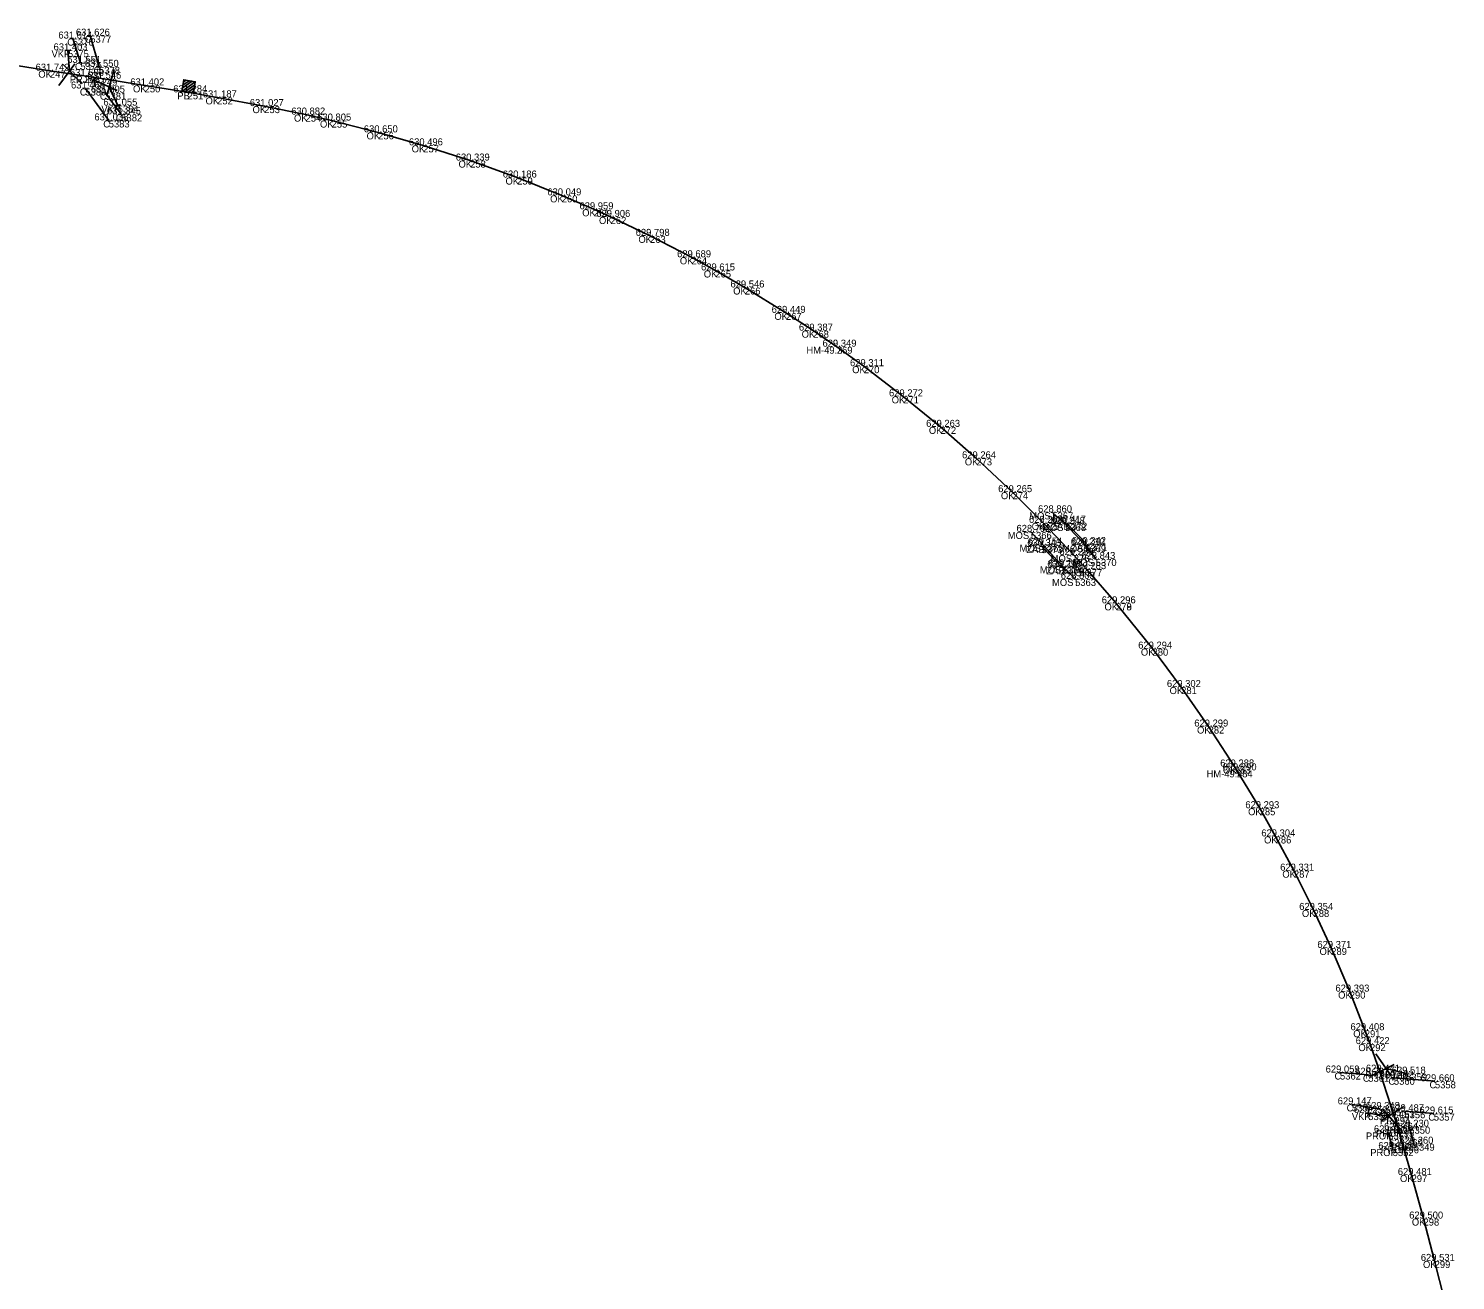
# Model space of a CAD drawing. Extents: x -631472 to -620808, y -1122356 to -1115125.
# Drawn here: x -629803.1 to -629559.3, y -1115505.1 to -1115291.1 of the extents above; entities that cross this region are included whole.
import ezdxf

# ---------------------------------------------------------------- set-up
doc = ezdxf.new("R2010")
doc.units = 0
for name, color, linetype in [('Vrstva 1', 7, 'Continuous'), ('Vrstva 17', 7, 'Continuous'), ('Vrstva 18', 7, 'Continuous'), ('Vrstva 3', 7, 'Continuous'), ('Vrstva 4', 7, 'Continuous'), ('Vrstva 51', 7, 'Continuous'), ('Vrstva 60', 7, 'Continuous'), ('Vrstva 61', 7, 'Continuous'), ('Vrstva 62', 7, 'Continuous')]:
    doc.layers.add(name, color=color, linetype=linetype)

msp = doc.modelspace()

# ---------------------------------------------------------------- linework, layer by layer
at = {"layer": 'Vrstva 1'}
msp.add_lwpolyline([(-629807.63, -1115297.05), (-629799.41, -1115298.32), (-629793.54, -1115299.22), (-629790.58, -1115299.68), (-629783.23, -1115300.83), (-629775.89, -1115302.01), (-629770.85, -1115302.88), (-629762.81, -1115304.37), (-629755.74, -1115305.82), (-629751.29, -1115306.84), (-629743.34, -1115308.86), (-629735.64, -1115311.08), (-629727.63, -1115313.68), (-629719.61, -1115316.58), (-629711.98, -1115319.63), (-629706.5, -1115322.01), (-629703.63, -1115323.31), (-629696.9, -1115326.55), (-629689.83, -1115330.21), (-629685.74, -1115332.46), (-629680.71, -1115335.37), (-629673.68, -1115339.71), (-629669.02, -1115342.75), (-629664.99, -1115345.49), (-629660.39, -1115348.82), (-629653.64, -1115353.98), (-629647.29, -1115359.19), (-629641.15, -1115364.57), (-629634.97, -1115370.35), (-629629.72, -1115375.6), (-629624.52, -1115381.1), (-629622.34, -1115383.51), (-629617.29, -1115389.35), (-629617.29, -1115389.36), (-629611.06, -1115397.09), (-629606.17, -1115403.66), (-629601.48, -1115410.41), (-629597.04, -1115417.24), (-629596.64, -1115417.9), (-629592.76, -1115424.37), (-629590.03, -1115429.19), (-629586.91, -1115435.04), (-629583.56, -1115441.75), (-629580.54, -1115448.25), (-629577.37, -1115455.71), (-629574.8, -1115462.31), (-629573.91, -1115464.68), (-629572.25, -1115469.4), (-629569.72, -1115477.19), (-629569.06, -1115479.33), (-629568.23, -1115482.13), (-629566.81, -1115487.06), (-629564.77, -1115494.5), (-629562.87, -1115501.74), (-629561.17, -1115508.42)], dxfattribs=at)
at = {"layer": 'Vrstva 17'}
for p, q in [((-629625.79, -1115375.58), (-629622.37, -1115379.21)), ((-629630.01, -1115379.57), (-629626.59, -1115383.19))]:
    msp.add_line(p, q, dxfattribs=at)
at = {"layer": 'Vrstva 18'}
for p, q in [((-629570.79, -1115479.77), (-629570.04, -1115482.62)), ((-629567.2, -1115478.8), (-629566.44, -1115481.7))]:
    msp.add_line(p, q, dxfattribs=at)
for points in [[(-629628.17, -1115373.8), (-629625.98, -1115375.78), (-629622.57, -1115379.4), (-629620.77, -1115381.77)], [(-629631.85, -1115377.14), (-629629.83, -1115379.33), (-629626.36, -1115383.03), (-629624.29, -1115385.18)]]:
    msp.add_lwpolyline(points, dxfattribs=at)
at = {"layer": 'Vrstva 3'}
for p, q in [((-629774.59, -1115300.2), (-629776.88, -1115301.85)), ((-629775.11, -1115300.11), (-629776.8, -1115301.33)), ((-629775.64, -1115300.03), (-629776.71, -1115300.8)), ((-629776.16, -1115299.94), (-629776.63, -1115300.28)), ((-629774.67, -1115300.72), (-629776.36, -1115301.94)), ((-629774.76, -1115301.24), (-629775.83, -1115302.02)), ((-629774.84, -1115301.77), (-629775.31, -1115302.11))]:
    msp.add_line(p, q, dxfattribs=at)
msp.add_lwpolyline([(-629774.91, -1115302.17), (-629776.88, -1115301.85), (-629776.56, -1115299.88), (-629774.59, -1115300.2)], close=True, dxfattribs=at)
at = {"layer": 'Vrstva 4'}
for p, q in [((-629795.84, -1115294.82), (-629796.83, -1115294.89)), ((-629795.16, -1115297.12), (-629797.89, -1115300.84)), ((-629793.9, -1115300.54), (-629797.16, -1115297.27)), ((-629796.34, -1115294.85), (-629796.07, -1115298.34)), ((-629793.54, -1115299.22), (-629790.58, -1115299.68)), ((-629789.72, -1115302.56), (-629788.45, -1115298.13)), ((-629792.08, -1115299.8), (-629787.9, -1115301.73)), ((-629787.83, -1115304.28), (-629789.29, -1115301.1)), ((-629788.28, -1115304.49), (-629787.37, -1115304.07)), ((-629570.27, -1115470.11), (-629572.9, -1115466.32)), ((-629573.91, -1115470.2), (-629569.77, -1115468.17)), ((-629572.25, -1115469.4), (-629569.72, -1115477.19)), ((-629567.74, -1115469.73), (-629571.13, -1115468.85)), ((-629567.87, -1115470.21), (-629567.62, -1115469.25)), ((-629574.14, -1115475.97), (-629574.28, -1115476.96)), ((-629574.21, -1115476.47), (-629570.75, -1115476.98)), ((-629568.13, -1115475.34), (-629572.03, -1115477.8)), ((-629571.74, -1115475.82), (-629568.72, -1115479.3))]:
    msp.add_line(p, q, dxfattribs=at)
at = {"layer": 'Vrstva 51'}
for p, q in [((-629792.52, -1115292.33), (-629791.02, -1115297.66)), ((-629795.52, -1115292.83), (-629794.21, -1115296.99)), ((-629793.36, -1115301.36), (-629789.37, -1115306.82)), ((-629789.95, -1115302.08), (-629787.22, -1115305.77)), ((-629579.04, -1115469.54), (-629574.2, -1115469.92)), ((-629569.83, -1115470.43), (-629562.82, -1115471.04)), ((-629576.98, -1115474.99), (-629572.15, -1115475.77)), ((-629563.01, -1115476.55), (-629568.04, -1115476.16))]:
    msp.add_line(p, q, dxfattribs=at)
at = {"layer": 'Vrstva 60'}
for p, q in [((-629799.41, -1115298.32), (-629799.41, -1115298.32)), ((-629793.54, -1115299.22), (-629793.54, -1115299.22)), ((-629790.58, -1115299.68), (-629790.58, -1115299.68)), ((-629783.23, -1115300.83), (-629783.23, -1115300.83)), ((-629775.89, -1115302.01), (-629775.89, -1115302.01)), ((-629770.85, -1115302.88), (-629770.85, -1115302.88)), ((-629762.81, -1115304.37), (-629762.81, -1115304.37)), ((-629755.74, -1115305.82), (-629755.74, -1115305.82)), ((-629751.29, -1115306.84), (-629751.29, -1115306.84)), ((-629743.34, -1115308.86), (-629743.34, -1115308.86)), ((-629735.64, -1115311.08), (-629735.64, -1115311.08)), ((-629727.63, -1115313.68), (-629727.63, -1115313.68)), ((-629719.61, -1115316.58), (-629719.61, -1115316.58)), ((-629711.98, -1115319.63), (-629711.98, -1115319.63)), ((-629706.5, -1115322.01), (-629706.5, -1115322.01)), ((-629703.63, -1115323.31), (-629703.63, -1115323.31)), ((-629696.9, -1115326.55), (-629696.9, -1115326.55)), ((-629689.83, -1115330.21), (-629689.83, -1115330.21)), ((-629685.74, -1115332.46), (-629685.74, -1115332.46)), ((-629680.71, -1115335.37), (-629680.71, -1115335.37)), ((-629673.68, -1115339.71), (-629673.68, -1115339.71)), ((-629669.02, -1115342.75), (-629669.02, -1115342.75)), ((-629664.99, -1115345.49), (-629664.99, -1115345.49)), ((-629660.39, -1115348.82), (-629660.39, -1115348.82)), ((-629653.64, -1115353.98), (-629653.64, -1115353.98)), ((-629647.29, -1115359.19), (-629647.29, -1115359.19)), ((-629641.15, -1115364.57), (-629641.15, -1115364.57)), ((-629634.97, -1115370.35), (-629634.97, -1115370.35)), ((-629629.72, -1115375.6), (-629629.72, -1115375.6)), ((-629624.52, -1115381.1), (-629624.52, -1115381.1)), ((-629622.34, -1115383.51), (-629622.34, -1115383.51)), ((-629617.29, -1115389.35), (-629617.29, -1115389.35)), ((-629617.29, -1115389.36), (-629617.29, -1115389.36)), ((-629611.06, -1115397.09), (-629611.06, -1115397.09)), ((-629606.17, -1115403.66), (-629606.17, -1115403.66)), ((-629601.48, -1115410.41), (-629601.48, -1115410.41)), ((-629597.04, -1115417.24), (-629597.04, -1115417.24)), ((-629596.64, -1115417.9), (-629596.64, -1115417.9)), ((-629592.76, -1115424.37), (-629592.76, -1115424.37)), ((-629590.03, -1115429.19), (-629590.03, -1115429.19)), ((-629586.91, -1115435.04), (-629586.91, -1115435.04)), ((-629583.56, -1115441.75), (-629583.56, -1115441.75)), ((-629580.54, -1115448.25), (-629580.54, -1115448.25)), ((-629577.37, -1115455.71), (-629577.37, -1115455.71)), ((-629574.8, -1115462.31), (-629574.8, -1115462.31)), ((-629573.91, -1115464.68), (-629573.91, -1115464.68)), ((-629572.25, -1115469.4), (-629572.25, -1115469.4)), ((-629569.72, -1115477.19), (-629569.72, -1115477.19)), ((-629569.06, -1115479.33), (-629569.06, -1115479.33)), ((-629568.23, -1115482.13), (-629568.23, -1115482.13)), ((-629566.81, -1115487.06), (-629566.81, -1115487.06)), ((-629564.77, -1115494.5), (-629564.77, -1115494.5)), ((-629562.87, -1115501.74), (-629562.87, -1115501.74))]:
    msp.add_line(p, q, dxfattribs=at)

# ---------------------------------------------------------------- texts
for s, p in [('5377', (-629792.52, -1115293.53)), ('5375', (-629796.34, -1115296.05)), ('5376', (-629795.52, -1115294.03)), ('5379', (-629794.21, -1115298.19)), ('247', (-629799.41, -1115299.52)), ('248', (-629793.54, -1115300.42)), ('5378', (-629791.02, -1115298.86)), ('249', (-629790.58, -1115300.88)), ('5380', (-629793.36, -1115302.56)), ('5381', (-629789.95, -1115303.28)), ('250', (-629783.23, -1115302.03)), ('251', (-629775.89, -1115303.21)), ('5384', (-629787.83, -1115305.48)), ('252', (-629770.85, -1115304.08)), ('253', (-629762.81, -1115305.57)), ('5383', (-629789.37, -1115308.02)), ('5382', (-629787.22, -1115306.97)), ('254', (-629755.74, -1115307.02)), ('255', (-629751.29, -1115308.04)), ('256', (-629743.34, -1115310.06)), ('257', (-629735.64, -1115312.28)), ('258', (-629727.63, -1115314.88)), ('259', (-629719.61, -1115317.78)), ('260', (-629711.98, -1115320.83)), ('261', (-629706.5, -1115323.21)), ('262', (-629703.63, -1115324.51)), ('263', (-629696.9, -1115327.75)), ('264', (-629689.83, -1115331.41)), ('265', (-629685.74, -1115333.66)), ('266', (-629680.71, -1115336.57)), ('267', (-629673.68, -1115340.91)), ('268', (-629669.02, -1115343.95)), ('269', (-629664.99, -1115346.69)), ('270', (-629660.39, -1115350.02)), ('271', (-629653.64, -1115355.18)), ('272', (-629647.29, -1115360.39)), ('273', (-629641.15, -1115365.77)), ('274', (-629634.97, -1115371.55)), ('5367', (-629628.17, -1115375)), ('5366', (-629631.85, -1115378.34)), ('275', (-629629.72, -1115376.8)), ('5368', (-629625.98, -1115376.98)), ('5372', (-629625.79, -1115376.78)), ('5373', (-629630.01, -1115380.77)), ('5365', (-629629.83, -1115380.53)), ('5369', (-629622.57, -1115380.6)), ('5371', (-629622.37, -1115380.41)), ('276', (-629624.52, -1115382.3)), ('5370', (-629620.77, -1115382.98)), ('5374', (-629626.59, -1115384.39)), ('5364', (-629626.36, -1115384.24)), ('277', (-629622.34, -1115384.71)), ('5363', (-629624.29, -1115386.38)), ('278', (-629617.29, -1115390.55)), ('279', (-629617.29, -1115390.56)), ('280', (-629611.06, -1115398.29)), ('281', (-629606.17, -1115404.86)), ('282', (-629601.48, -1115411.61)), ('283', (-629597.04, -1115418.44)), ('284', (-629596.64, -1115419.1)), ('285', (-629592.76, -1115425.57)), ('286', (-629590.03, -1115430.39)), ('287', (-629586.91, -1115436.24)), ('288', (-629583.56, -1115442.95)), ('289', (-629580.54, -1115449.45)), ('290', (-629577.37, -1115456.91)), ('291', (-629574.8, -1115463.51)), ('292', (-629573.91, -1115465.88)), ('5362', (-629579.04, -1115470.74)), ('5361', (-629574.2, -1115471.12)), ('293', (-629572.25, -1115470.6)), ('5359', (-629567.74, -1115470.93)), ('5360', (-629569.83, -1115471.63)), ('5358', (-629562.82, -1115472.24)), ('5354', (-629576.98, -1115476.19)), ('5353', (-629574.21, -1115477.67)), ('5355', (-629572.15, -1115476.98)), ('294', (-629569.72, -1115478.39)), ('5356', (-629568.04, -1115477.36)), ('5357', (-629563.01, -1115477.76)), ('5351', (-629570.79, -1115480.98)), ('295', (-629569.06, -1115480.53)), ('5350', (-629567.2, -1115480)), ('296', (-629568.23, -1115483.33)), ('5349', (-629566.44, -1115482.9)), ('5352', (-629570.04, -1115483.82)), ('297', (-629566.81, -1115488.26)), ('298', (-629564.77, -1115495.7)), ('299', (-629562.87, -1115502.94))]:
    msp.add_text(s, height=1.2, dxfattribs=at).set_placement(p)
at = {"layer": 'Vrstva 61'}
for s, p in [('631.614', (-629797.97, -1115292.83)), ('631.626', (-629794.98, -1115292.33)), ('631.403', (-629798.79, -1115294.85)), ('631.742', (-629801.86, -1115298.32)), ('631.551', (-629796.46, -1115296.99)), ('631.550', (-629793.47, -1115297.66)), ('631.608', (-629796, -1115299.22)), ('631.546', (-629793.03, -1115299.68)), ('631.402', (-629785.68, -1115300.83)), ('631.466', (-629795.81, -1115301.36)), ('631.305', (-629792.4, -1115302.08)), ('631.284', (-629778.34, -1115302.01)), ('631.187', (-629773.3, -1115302.88)), ('631.055', (-629790.28, -1115304.28)), ('631.345', (-629789.68, -1115305.77)), ('631.027', (-629765.27, -1115304.37)), ('631.036', (-629791.82, -1115306.82)), ('630.882', (-629758.19, -1115305.82)), ('630.805', (-629753.75, -1115306.84)), ('630.650', (-629745.79, -1115308.86)), ('630.496', (-629738.09, -1115311.08)), ('630.339', (-629730.09, -1115313.68)), ('630.186', (-629722.06, -1115316.58)), ('630.049', (-629714.44, -1115319.63)), ('629.959', (-629708.95, -1115322.01)), ('629.906', (-629706.08, -1115323.31)), ('629.798', (-629699.35, -1115326.55)), ('629.689', (-629692.28, -1115330.21)), ('629.615', (-629688.19, -1115332.46)), ('629.546', (-629683.16, -1115335.37)), ('629.449', (-629676.13, -1115339.71)), ('629.387', (-629671.47, -1115342.75)), ('629.349', (-629667.44, -1115345.49)), ('629.311', (-629662.74, -1115348.82)), ('629.272', (-629656.08, -1115353.98)), ('629.263', (-629649.74, -1115359.19)), ('629.264', (-629643.6, -1115364.57)), ('629.265', (-629637.43, -1115370.35)), ('628.860', (-629630.62, -1115373.8)), ('629.264', (-629632.17, -1115375.6)), ('629.248', (-629628.43, -1115375.78)), ('630.417', (-629628.24, -1115375.58)), ('628.792', (-629634.3, -1115377.14)), ('630.343', (-629632.46, -1115379.57)), ('629.154', (-629632.28, -1115379.33)), ('629.280', (-629626.97, -1115381.1)), ('629.210', (-629625.02, -1115379.4)), ('630.342', (-629624.82, -1115379.21)), ('630.298', (-629629.04, -1115383.19)), ('629.163', (-629628.81, -1115383.03)), ('629.283', (-629624.79, -1115383.51)), ('628.843', (-629623.22, -1115381.77)), ('628.803', (-629626.74, -1115385.18)), ('629.296', (-629619.75, -1115389.35)), ('629.296', (-629619.74, -1115389.36)), ('629.294', (-629613.51, -1115397.09)), ('629.302', (-629608.61, -1115403.66)), ('629.299', (-629603.93, -1115410.41)), ('629.288', (-629599.5, -1115417.24)), ('629.290', (-629599.09, -1115417.9)), ('629.293', (-629595.21, -1115424.37)), ('629.304', (-629592.48, -1115429.19)), ('629.331', (-629589.26, -1115435.04)), ('629.354', (-629586.01, -1115441.75)), ('629.371', (-629582.9, -1115448.25)), ('629.393', (-629579.82, -1115455.71)), ('629.408', (-629577.25, -1115462.31)), ('629.422', (-629576.36, -1115464.68)), ('629.059', (-629581.49, -1115469.54)), ('629.291', (-629576.45, -1115469.92)), ('629.441', (-629574.61, -1115469.4)), ('629.492', (-629572.28, -1115470.43)), ('629.518', (-629570.2, -1115469.73)), ('629.660', (-629565.27, -1115471.04)), ('629.147', (-629579.43, -1115474.99)), ('629.348', (-629574.61, -1115475.77)), ('629.487', (-629570.49, -1115476.16)), ('629.252', (-629576.66, -1115476.47)), ('629.461', (-629572.08, -1115477.19)), ('629.230', (-629569.65, -1115478.8)), ('629.615', (-629565.47, -1115476.55)), ('629.156', (-629573.24, -1115479.77)), ('629.464', (-629571.51, -1115479.33)), ('629.166', (-629572.49, -1115482.62)), ('629.469', (-629570.68, -1115482.13)), ('629.260', (-629568.89, -1115481.7)), ('629.481', (-629569.16, -1115487.06)), ('629.500', (-629567.22, -1115494.5)), ('629.531', (-629565.23, -1115501.74))]:
    msp.add_text(s, height=1.2, dxfattribs=at).set_placement(p)
at = {"layer": 'Vrstva 62'}
for s, p in [('C', (-629793.46, -1115293.53)), ('C', (-629796.45, -1115294.03)), ('VKR', (-629799.14, -1115296.05)), ('C', (-629795.14, -1115298.19)), ('OK', (-629801.4, -1115299.52)), ('PRJ', (-629796.03, -1115300.42)), ('PRJ', (-629793.07, -1115300.88)), ('C', (-629791.96, -1115298.86)), ('C', (-629794.3, -1115302.56)), ('C', (-629790.88, -1115303.28)), ('OK', (-629785.22, -1115302.03)), ('PB', (-629777.66, -1115303.21)), ('VKR', (-629790.63, -1115305.48)), ('OK', (-629772.83, -1115304.08)), ('OK', (-629764.8, -1115305.57)), ('C', (-629790.31, -1115308.02)), ('C', (-629788.16, -1115306.97)), ('OK', (-629757.72, -1115307.02)), ('OK', (-629753.28, -1115308.04)), ('OK', (-629745.32, -1115310.06)), ('OK', (-629737.62, -1115312.28)), ('OK', (-629729.62, -1115314.88)), ('OK', (-629721.59, -1115317.78)), ('OK', (-629713.97, -1115320.83)), ('OK', (-629708.49, -1115323.21)), ('OK', (-629705.62, -1115324.51)), ('OK', (-629698.89, -1115327.75)), ('OK', (-629691.81, -1115331.41)), ('OK', (-629687.72, -1115333.66)), ('OK', (-629682.7, -1115336.57)), ('OK', (-629675.66, -1115340.91)), ('OK', (-629671, -1115343.95)), ('HM-49.3', (-629670.19, -1115346.69)), ('OK', (-629662.37, -1115350.02)), ('OK', (-629655.62, -1115355.18)), ('OK', (-629649.27, -1115360.39)), ('OK', (-629643.13, -1115365.77)), ('OK', (-629636.96, -1115371.55)), ('MOST', (-629632.12, -1115375)), ('MOST', (-629635.79, -1115378.34)), ('OK', (-629631.7, -1115376.8)), ('MOST', (-629629.93, -1115376.98)), ('ZAB', (-629628.39, -1115376.78)), ('MOST', (-629633.78, -1115380.53)), ('ZAB', (-629632.61, -1115380.77)), ('MOST', (-629626.52, -1115380.6)), ('ZAB', (-629624.97, -1115380.41)), ('MOST', (-629628.46, -1115382.3)), ('MOST', (-629624.71, -1115382.98)), ('MOST', (-629630.3, -1115384.24)), ('ZAB', (-629629.19, -1115384.39)), ('OK', (-629624.32, -1115384.71)), ('MOST', (-629628.23, -1115386.38)), ('OK', (-629619.28, -1115390.55)), ('OK', (-629619.27, -1115390.56)), ('OK', (-629613.05, -1115398.29)), ('OK', (-629608.15, -1115404.86)), ('OK', (-629603.46, -1115411.61)), ('HM-49.4', (-629601.84, -1115419.1)), ('OK', (-629599.03, -1115418.44)), ('OK', (-629594.74, -1115425.57)), ('OK', (-629592.01, -1115430.39)), ('OK', (-629588.89, -1115436.24)), ('OK', (-629585.54, -1115442.95)), ('OK', (-629582.53, -1115449.45)), ('OK', (-629579.36, -1115456.91)), ('OK', (-629576.78, -1115463.51)), ('OK', (-629575.9, -1115465.88)), ('C', (-629579.98, -1115470.74)), ('C', (-629575.13, -1115471.12)), ('PRJ', (-629574.74, -1115470.6)), ('VKR', (-629570.55, -1115470.93)), ('C', (-629570.77, -1115471.63)), ('C', (-629563.75, -1115472.24)), ('C', (-629577.91, -1115476.19)), ('VKR', (-629577.02, -1115477.67)), ('C', (-629573.09, -1115476.98)), ('PRJ', (-629572.21, -1115478.39)), ('C', (-629568.98, -1115477.36)), ('C', (-629563.95, -1115477.76)), ('PROP', (-629574.62, -1115480.98)), ('PROP', (-629572.9, -1115480.53)), ('PROP', (-629571.04, -1115480)), ('PROP', (-629572.06, -1115483.33)), ('PROP', (-629570.27, -1115482.9)), ('PROP', (-629573.88, -1115483.82)), ('OK', (-629568.79, -1115488.26)), ('OK', (-629566.76, -1115495.7)), ('OK', (-629564.86, -1115502.94))]:
    msp.add_text(s, height=1.2, dxfattribs=at).set_placement(p)

doc.saveas('drawing.dxf')
